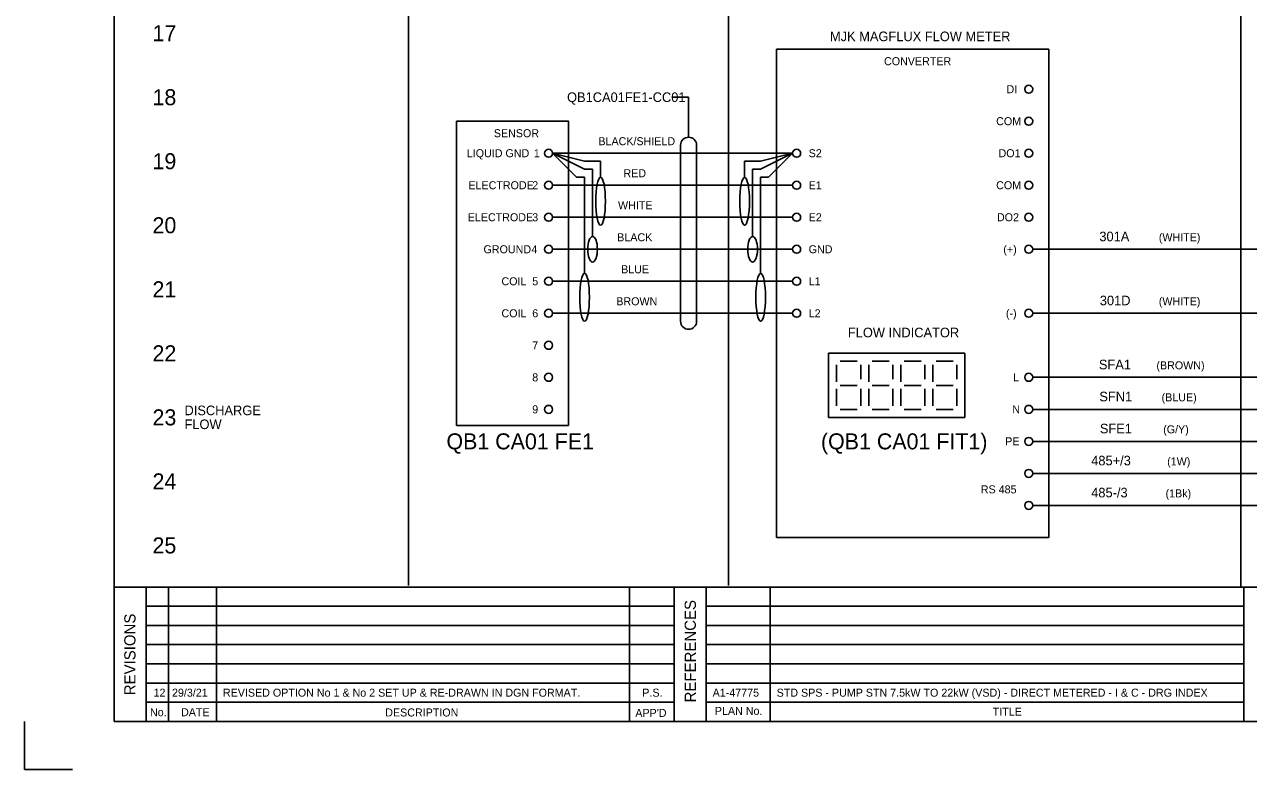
# Model space of a CAD drawing. Extents: x 0 to 841, y 0 to 594.
# Drawn here: x 0 to 382.4, y 0 to 232.7 of the extents above; entities that cross this region are included whole.
import ezdxf

# ---------------------------------------------------------------- set-up
doc = ezdxf.new("R2010")
doc.units = 0
for name, color, linetype in [('A1BORDER', 7, 'Continuous'), ('Level 1', 7, 'Continuous'), ('Level 10', 7, 'Continuous'), ('Level 2', 7, 'Continuous')]:
    doc.layers.add(name, color=color, linetype=linetype)

msp = doc.modelspace()

# ---------------------------------------------------------------- linework, layer by layer
at = {"layer": 'A1BORDER'}
for p, q in [((28, 581), (28, 15)), ((28, 57), (829, 57)), ((38, 15), (38, 57)), ((45, 15), (45, 57)), ((60, 15), (60, 57)), ((189, 15), (189, 57)), ((203, 15), (203, 57)), ((213, 15), (213, 57)), ((233, 15), (233, 57)), ((381, 15), (381, 57)), ((203, 51), (38, 51)), ((213, 51), (381, 51)), ((203, 45), (38, 45)), ((213, 45), (381, 45)), ((203, 39), (38, 39)), ((213, 39), (381, 39)), ((203, 33), (38, 33)), ((213, 33), (381, 33)), ((38, 27), (203, 27)), ((213, 27), (381, 27)), ((203, 21), (38, 21)), ((213, 21), (381, 21)), ((0, 0), (0, 15)), ((829, 15), (28, 15)), ((0, 0), (15, 0))]:
    msp.add_line(p, q, dxfattribs=at)
at = {"layer": 'Level 1'}
for p, q in [((120, 57.5), (120, 581)), ((220, 57.5), (220, 581)), ((380, 57), (380, 572.5)), ((312.5, 212.5), (312.5, 212.5)), ((315, 212.5), (315, 212.5)), ((207.5, 210), (202.5, 210)), ((207.5, 210), (207.5, 197.5)), ((312.5, 202.5), (312.5, 202.5)), ((315, 202.5), (315, 202.5)), ((162.5, 192.5), (162.5, 192.5)), ((240, 192.5), (165, 192.5)), ((165, 192.5), (165, 192.5)), ((175, 190), (165, 192.5)), ((175, 187.5), (165, 192.5)), ((172.5, 185), (165, 192.5)), ((205, 195), (205, 140)), ((210, 195), (210, 140)), ((230, 190), (240, 192.5)), ((230, 187.5), (240, 192.5)), ((232.5, 185), (240, 192.5)), ((240, 192.5), (240, 192.5)), ((242.5, 192.5), (242.5, 192.5)), ((312.5, 192.5), (312.5, 192.5)), ((315, 192.5), (315, 192.5)), ((180, 190), (175, 190)), ((175, 187.5), (177.5, 187.5)), ((177.5, 166.5), (177.5, 187.5)), ((180, 185), (180, 190)), ((225, 185), (225, 190)), ((225, 190), (230, 190)), ((227.5, 166.5), (227.5, 187.5)), ((230, 187.5), (227.5, 187.5)), ((175, 185), (172.5, 185)), ((175, 155), (175, 185)), ((230, 155), (230, 185)), ((230, 185), (232.5, 185)), ((162.5, 182.5), (162.5, 182.5)), ((240, 182.5), (165, 182.5)), ((165, 182.5), (165, 182.5)), ((240, 182.5), (240, 182.5)), ((242.5, 182.5), (242.5, 182.5)), ((312.5, 182.5), (312.5, 182.5)), ((315, 182.5), (315, 182.5)), ((162.5, 172.5), (162.5, 172.5)), ((240, 172.5), (165, 172.5)), ((165, 172.5), (165, 172.5)), ((240, 172.5), (240, 172.5)), ((242.5, 172.5), (242.5, 172.5)), ((312.5, 172.5), (312.5, 172.5)), ((315, 172.5), (315, 172.5)), ((162.5, 162.5), (162.5, 162.5)), ((165, 162.5), (165, 162.5)), ((177.5, 162.5), (165, 162.5)), ((240, 162.5), (165, 162.5)), ((240, 162.5), (240, 162.5)), ((242.5, 162.5), (242.5, 162.5)), ((312.5, 162.5), (312.5, 162.5)), ((315, 162.5), (315, 162.5)), ((640, 162.5), (315, 162.5)), ((162.5, 152.5), (162.5, 152.5)), ((240, 152.5), (165, 152.5)), ((165, 152.5), (165, 152.5)), ((240, 152.5), (240, 152.5)), ((242.5, 152.5), (242.5, 152.5)), ((162.5, 142.5), (162.5, 142.5)), ((240, 142.5), (165, 142.5)), ((165, 142.5), (165, 142.5)), ((240, 142.5), (240, 142.5)), ((242.5, 142.5), (242.5, 142.5)), ((312.5, 142.5), (312.5, 142.5)), ((315, 142.5), (315, 142.5)), ((570, 142.5), (315, 142.5)), ((162.5, 132.5), (162.5, 132.5)), ((165, 132.5), (165, 132.5)), ((162.5, 122.5), (162.5, 122.5)), ((165, 122.5), (165, 122.5)), ((312.5, 122.5), (312.5, 122.5)), ((315, 122.5), (315, 122.5)), ((315, 122.5), (760, 122.5)), ((162.5, 112.5), (162.5, 112.5)), ((165, 112.5), (165, 112.5)), ((312.5, 112.5), (312.5, 112.5)), ((315, 112.5), (315, 112.5)), ((315, 112.5), (760, 112.5)), ((312.5, 102.5), (312.5, 102.5)), ((315, 102.5), (315, 102.5)), ((315, 102.5), (760, 102.5)), ((315, 92.5), (640, 92.5)), ((315, 82.5), (640, 82.5))]:
    msp.add_line(p, q, dxfattribs=at)
for points in [[(320, 72.5), (235, 72.5), (235, 225), (320, 225)], [(170, 107.5), (135, 107.5), (135, 202.5), (170, 202.5)], [(251.25, 130), (293.75, 130), (293.75, 110), (251.25, 110)]]:
    msp.add_lwpolyline(points, close=True, dxfattribs=at)
for centre, start, end in [((207.5, 195), 0, 180), ((207.5, 140), 180, 0)]:
    msp.add_arc(centre, 2.5, start, end, dxfattribs=at)
for centre, major_axis, ratio in [((180, 177.5), (0, -7.5), 0.2), ((225, 177.5), (0, 7.5), 0.2), ((177.5, 162.5), (0, -4), 0.375), ((227.5, 162.5), (0, 4), 0.375), ((175, 147.5), (0, -7.5), 0.2), ((230, 147.5), (0, 7.5), 0.2)]:
    msp.add_ellipse(centre, major_axis=major_axis, ratio=ratio, dxfattribs=at)
at = {"layer": 'Level 10'}
for centre in [(313.75, 212.5), (313.75, 202.5), (163.75, 192.5), (241.25, 192.5), (313.75, 192.5), (163.75, 182.5), (241.25, 182.5), (313.75, 182.5), (163.75, 172.5), (241.25, 172.5), (313.75, 172.5), (163.75, 162.5), (241.25, 162.5), (313.75, 162.5), (163.75, 152.5), (241.25, 152.5), (163.75, 142.5), (241.25, 142.5), (313.75, 142.5), (163.75, 132.5), (163.75, 122.5), (313.75, 122.5), (163.75, 112.5), (313.75, 112.5), (313.75, 102.5), (313.75, 92.5), (313.75, 82.5)]:
    msp.add_circle(centre, 1.25, dxfattribs=at)
at = {"layer": 'Level 2'}
for p, q in [((253.75, 126.38), (253.75, 121.13)), ((254.88, 127.5), (260.12, 127.5)), ((261.25, 126.38), (261.25, 121.88)), ((263.75, 126.38), (263.75, 121.13)), ((264.88, 127.5), (270.12, 127.5)), ((271.25, 126.38), (271.25, 121.88)), ((273.75, 126.38), (273.75, 121.13)), ((274.88, 127.5), (280.12, 127.5)), ((281.25, 126.38), (281.25, 121.88)), ((283.75, 126.38), (283.75, 121.13)), ((284.88, 127.5), (290.12, 127.5)), ((291.25, 126.38), (291.25, 121.88)), ((253.75, 118.88), (253.75, 113.63)), ((254.88, 120), (260.12, 120)), ((261.25, 118.88), (261.25, 113.63)), ((263.75, 118.88), (263.75, 113.63)), ((264.88, 120), (270.12, 120)), ((271.25, 118.88), (271.25, 113.63)), ((273.75, 118.88), (273.75, 113.63)), ((274.88, 120), (280.12, 120)), ((281.25, 118.88), (281.25, 113.63)), ((283.75, 118.88), (283.75, 113.63)), ((284.88, 120), (290.12, 120)), ((291.25, 118.88), (291.25, 113.63)), ((254.88, 112.5), (260.12, 112.5)), ((264.88, 112.5), (270.12, 112.5)), ((274.88, 112.5), (280.12, 112.5)), ((284.88, 112.5), (290.12, 112.5))]:
    msp.add_line(p, q, dxfattribs=at)

# ---------------------------------------------------------------- texts
at = {"layer": 'A1BORDER'}
for s, p in [('REFERENCES', (209.76, 20.96)), ('REVISIONS', (34.68, 23.2))]:
    msp.add_text(s, height=3.5, rotation=90, dxfattribs=at).set_placement(p)
for s, p in [('No.', (39.21, 16.65)), ('DATE', (48.92, 16.65)), ('PLAN No.', (215.69, 17.06)), ('TITLE', (302.5, 16.81)), ('DESCRIPTION', (112.71, 16.57)), ("APP'D", (190.85, 16.44))]:
    msp.add_text(s, height=2.5, dxfattribs=at).set_placement(p)
at = {"layer": 'Level 1'}
for s, height, p in [('17', 5, (40, 227.5)), ('MJK MAGFLUX FLOW METER', 3, (251.65, 227.5)), ('MJK MAGFLUX FLOW METER', 3, (251.65, 227.5)), ('CONVERTER', 2.5, (268.55, 220)), ('18', 5, (40, 207.5)), ('QB1CA01FE1-CC01', 3, (169.52, 208.5)), ('DI', 2.5, (306.81, 211.25)), ('COM', 2.5, (303.58, 201.25)), ('SENSOR', 2.5, (146.64, 197.5)), ('BLACK/SHIELD', 2.5, (179.3, 195)), ('19', 5, (40, 187.5)), ('LIQUID GND', 2.5, (138.2, 191.25)), ('1', 2.5, (159.13, 191.25)), ('S2', 2.5, (245, 191.25)), ('DO1', 2.5, (304.32, 191.25)), ('RED', 2.5, (187.14, 185)), ('ELECTRODE', 2.5, (138.69, 181.25)), ('2', 2.5, (158.64, 181.25)), ('E1', 2.5, (245, 181.25)), ('COM', 2.5, (303.58, 181.25)), ('WHITE', 2.5, (185.44, 175)), ('20', 5, (40, 167.5)), ('ELECTRODE', 2.5, (138.49, 171.25)), ('3', 2.5, (158.64, 171.25)), ('E2', 2.5, (245, 171.25)), ('DO2', 2.5, (303.83, 171.25)), ('BLACK', 2.5, (185.19, 165)), ('301A', 3, (335.82, 165)), ('(WHITE)', 2.5, (354.4, 165)), ('GROUND', 2.5, (143.42, 161.25)), ('4', 2.5, (158.39, 161.25)), ('GND', 2.5, (245, 161.25)), ('(+)', 2.5, (305.82, 161.25)), ('BLUE', 2.5, (186.41, 155)), ('COIL', 2.5, (149.02, 151.25)), ('5', 2.5, (158.64, 151.25)), ('L1', 2.5, (245, 151.25)), ('21', 5, (40, 147.5)), ('BROWN', 2.5, (184.9, 145)), ('301D', 3, (335.96, 145)), ('(WHITE)', 2.5, (354.4, 145)), ('COIL', 2.5, (149.03, 141.25)), ('6', 2.5, (158.64, 141.25)), ('L2', 2.5, (245, 141.25)), ('(-)', 2.5, (306.64, 141.25)), ('22', 5, (40, 127.5)), ('7', 2.5, (158.64, 131.25)), ('SFA1', 3, (335.67, 125)), ('(BROWN)', 2.5, (353.65, 125)), ('8', 2.5, (158.64, 121.25)), ('L', 2.5, (308.88, 121.25)), ('SFN1', 3, (335.81, 115)), ('(BLUE)', 2.5, (355.27, 115)), ('23', 5, (40, 107.5)), ('DISCHARGE', 3, (50, 110.67)), ('9', 2.5, (158.64, 111.25)), ('N', 2.5, (308.62, 111.25)), ('FLOW', 3, (50, 106.33)), ('SFE1', 3, (335.97, 105)), ('(G/Y)', 2.5, (355.77, 105)), ('QB1 CA01 FE1', 5, (131.83, 100)), ('(QB1 CA01 FIT1)', 5, (248.84, 100)), ('PE', 2.5, (306.41, 101.25)), ('485+/3', 3, (333.28, 95)), ('(1W)', 2.5, (357.01, 95)), ('24', 5, (40, 87.5)), ('RS 485', 2.5, (298.79, 86.25)), ('485-/3', 3, (333.28, 85)), ('(1Bk)', 2.5, (356.51, 85)), ('25', 5, (40, 67.5)), ('12', 2.5, (40.32, 22.75)), ('29/3/21', 2.5, (46.09, 22.75)), ('REVISED OPTION No 1 & No 2 SET UP & RE-DRAWN IN DGN FORMAT.', 2.5, (62, 22.75)), ('P.S.', 2.5, (193.02, 22.75)), ('A1-47775', 2.5, (215, 22.75)), ('STD SPS - PUMP STN 7.5kW TO 22kW (VSD) - DIRECT METERED - I & C - DRG INDEX', 2.5, (235, 22.75))]:
    msp.add_text(s, height=height, dxfattribs=at).set_placement(p)
at = {"layer": 'Level 2'}
msp.add_text('FLOW INDICATOR', height=3, dxfattribs=at).set_placement((257.26, 135))

doc.saveas('drawing.dxf')
